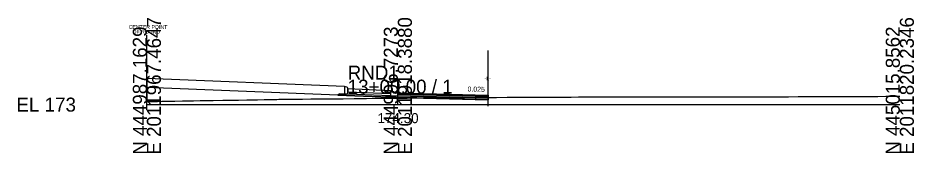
# Model space of a CAD drawing. Extents: x -26 to 153, y -10 to 6017.
# Drawn here: x -25.7 to 152.8, y 5990.3 to 6017.3 of the extents above; entities that cross this region are included whole.
import ezdxf

# ---------------------------------------------------------------- set-up
doc = ezdxf.new("R2010")
doc.units = 0
for name, color, linetype in [('Exist Cross Section Cell', 7, 'Continuous'), ('Exist XS Ground Line', 7, 'Continuous'), ('Prop CMT Conc Surface', 7, 'Continuous'), ('Prop CMT Concrete Structures', 7, 'Continuous'), ('Prop CMT Pvmt Course 1', 7, 'Continuous'), ('Prop CMT Pvmt Course 1 CG', 7, 'Continuous'), ('Prop CMT Pvmt Course 2', 7, 'Continuous'), ('Prop CMT Pvmt Course 3', 7, 'Continuous'), ('Prop CMT Pvmt Surface', 7, 'Continuous'), ('Prop CMT Shear Line', 7, 'Continuous'), ('Prop CMT Shear Line Text', 7, 'Continuous'), ('Prop CMT Slope Grass', 7, 'Continuous'), ('Prop CMT Subgrade Earthwork', 7, 'Continuous'), ('Prop XS Earthwork Shape', 7, 'Continuous'), ('Prop XS SE Text', 7, 'Continuous'), ('Scratch_Level_1', 7, 'Continuous')]:
    doc.layers.add(name, color=color, linetype=linetype)

msp = doc.modelspace()

# ---------------------------------------------------------------- linework, layer by layer
at = {"layer": 'Exist Cross Section Cell'}
for p, q in [((50, 6000), (50, 6004.99)), ((0, 6000), (50, 6000)), ((50, 6000), (150, 6000))]:
    msp.add_line(p, q, dxfattribs=at)
at = {"layer": 'Exist XS Ground Line'}
msp.add_lwpolyline([(0, 6000.62), (0.45, 6000.63), (2.11, 6000.65), (3, 6000.67), (4.98, 6000.7), (5.55, 6000.71), (7.12, 6000.74), (8.1, 6000.76), (9.26, 6000.78), (10.64, 6000.81), (12.71, 6000.84), (13.19, 6000.85), (15.11, 6000.88), (15.9, 6000.89), (18.28, 6000.92), (19.89, 6000.95), (20.83, 6000.96), (22.02, 6000.98), (23.38, 6001.01), (24.17, 6001.02), (25.92, 6001.05), (26.29, 6001.06), (28.47, 6001.1), (30.56, 6001.12), (31.03, 6001.12), (32.69, 6001.14), (33.56, 6001.15), (34.86, 6001.16), (36.11, 6001.17), (36.95, 6001.18), (38.67, 6001.19), (39.09, 6001.19), (41.27, 6001.21), (43.35, 6001.23), (43.76, 6001.24), (45.48, 6001.26), (46.3, 6001.26), (47.61, 6001.28), (48.85, 6001.29), (50, 6001.3), (51.4, 6001.31), (51.87, 6001.32), (54.3, 6001.34), (55.99, 6001.35), (56.7, 6001.36), (58.04, 6001.37), (59.42, 6001.38), (60.16, 6001.39), (62.35, 6001.41), (63.53, 6001.42), (64.61, 6001.43), (65.76, 6001.43), (66.62, 6001.43), (67.07, 6001.43), (67.43, 6001.43), (69.22, 6001.44), (69.65, 6001.45), (71.78, 6001.46), (73.03, 6001.46), (74.32, 6001.47), (75.25, 6001.47), (76.79, 6001.47), (77.45, 6001.47), (79.59, 6001.48), (80.49, 6001.48), (81.95, 6001.5), (82.32, 6001.5), (84.52, 6001.52), (85.98, 6001.53), (87.06, 6001.53), (88.11, 6001.53), (89.6, 6001.54), (91.84, 6001.55), (92.38, 6001.55), (93.51, 6001.55), (94.98, 6001.55), (97.24, 6001.55), (98.77, 6001.56), (99.78, 6001.56), (101.3, 6001.56), (102.33, 6001.56), (104.45, 6001.57), (105.16, 6001.57), (106.62, 6001.57), (107.64, 6001.57), (110, 6001.57), (111.55, 6001.57), (112.53, 6001.57), (113.94, 6001.57), (115.07, 6001.57), (117.12, 6001.56), (117.63, 6001.56), (119.76, 6001.55), (120.26, 6001.55), (122.71, 6001.56), (123.44, 6001.57), (125.26, 6001.58), (126.6, 6001.59), (127.79, 6001.59), (129.78, 6001.6), (130.35, 6001.6), (132.9, 6001.61), (135.08, 6001.61), (135.71, 6001.61), (137.37, 6001.62), (138.48, 6001.62), (139.92, 6001.63), (141.52, 6001.64), (142.3, 6001.64), (143.1, 6001.64), (144.29, 6001.65), (144.69, 6001.65), (145.62, 6001.65), (147.19, 6001.66), (147.51, 6001.66), (150, 6001.66)], dxfattribs=at)
at = {"layer": 'Prop CMT Conc Surface'}
for points in [[(40, 6003.31), (39.96, 6003.41), (39.85, 6003.46), (39.34, 6003.64)], [(40, 6003.14), (40, 6003.31)], [(50, 6002.35), (49.25, 6002.37), (49.25, 6002.53), (48.5, 6002.78)]]:
    msp.add_lwpolyline(points, dxfattribs=at)
at = {"layer": 'Prop CMT Concrete Structures'}
for points in [[(40, 6003.31), (39.96, 6003.41), (39.85, 6003.46), (39.34, 6003.64)], [(39.34, 6003.64), (39.34, 6002.14)], [(40, 6003.14), (40, 6003.31)], [(40, 6002.14), (40, 6003.14)], [(40, 6003.14), (40, 6002.56)], [(48.5, 6002.78), (40, 6003.13)], [(40, 6002.54), (48.5, 6002.2)], [(50, 6002.35), (49.25, 6002.37), (49.25, 6002.53), (48.5, 6002.78)], [(48.5, 6002.78), (48.5, 6001.8)], [(48.5, 6002.2), (48.5, 6002.78)], [(50, 6001.77), (50, 6002.35)], [(39.34, 6002.14), (40, 6002.14)], [(48.5, 6001.8), (50, 6001.77)]]:
    msp.add_lwpolyline(points, dxfattribs=at)
at = {"layer": 'Prop CMT Pvmt Course 1'}
for points in [[(50, 6002.35), (68, 6001.9)], [(50, 6002.1), (50, 6002.35)], [(68, 6001.65), (50, 6002.1)], [(68, 6001.9), (68, 6001.65)]]:
    msp.add_lwpolyline(points, dxfattribs=at)
msp.add_lwpolyline([(50, 6002.1), (50, 6002.22), (50, 6002.22), (50, 6002.1)], close=True, dxfattribs=at)
at = {"layer": 'Prop CMT Pvmt Course 1 CG'}
for points in [[(50, 6001.43), (50, 6001.77)], [(68, 6000.98), (68, 6001.31)]]:
    msp.add_lwpolyline(points, dxfattribs=at)
at = {"layer": 'Prop CMT Pvmt Course 2'}
for points in [[(50, 6001.77), (50, 6002.1)], [(50, 6002.1), (68, 6001.65)], [(68, 6001.31), (50, 6001.77)], [(68, 6001.65), (68, 6001.31)]]:
    msp.add_lwpolyline(points, dxfattribs=at)
at = {"layer": 'Prop CMT Pvmt Course 3'}
for points in [[(40, 6002.14), (48.5, 6001.8)], [(50, 6001.77), (68, 6001.31)], [(50, 6001.43), (50, 6001.77)], [(68, 6000.98), (50, 6001.43)], [(68, 6001.31), (68, 6000.98)]]:
    msp.add_lwpolyline(points, dxfattribs=at)
at = {"layer": 'Prop CMT Pvmt Surface'}
msp.add_lwpolyline([(50, 6002.35), (68, 6001.9)], dxfattribs=at)
at = {"layer": 'Prop CMT Shear Line'}
for p, q in [((0, 5998.89), (0, 6013.89)), ((68, 5999.72), (68, 6004.74))]:
    msp.add_line(p, q, dxfattribs=at)
at = {"layer": 'Prop CMT Slope Grass'}
for p, q in [((39.34, 6003.63), (0, 6005.2)), ((38.06, 6001.91), (0, 6003.43))]:
    msp.add_line(p, q, dxfattribs=at)
at = {"layer": 'Prop CMT Subgrade Earthwork'}
for p, q in [((0, 6005.2), (0, 6000.62)), ((38.34, 6002.18), (38.06, 6001.91)), ((68, 6001.9), (68, 6001.44)), ((68, 6000.98), (68, 6001.44))]:
    msp.add_line(p, q, dxfattribs=at)
for points in [[(38.06, 6001.91), (50, 6001.43)], [(38.34, 6002.18), (39.34, 6002.14)], [(50, 6001.43), (68, 6000.98)]]:
    msp.add_lwpolyline(points, dxfattribs=at)
at = {"layer": 'Prop XS Earthwork Shape'}
for points in [[(50, 6001.3), (51.4, 6001.31), (51.87, 6001.32), (53.8, 6001.34), (50, 6001.43), (38.06, 6001.91), (0, 6003.43), (0, 6000.62), (0.45, 6000.63), (2.11, 6000.65), (3, 6000.67), (4.98, 6000.7), (5.55, 6000.71), (7.12, 6000.74), (8.1, 6000.76), (9.26, 6000.78), (10.64, 6000.81), (12.71, 6000.84), (13.19, 6000.85), (15.11, 6000.88), (15.9, 6000.89), (18.28, 6000.92), (19.89, 6000.95), (20.83, 6000.96), (22.02, 6000.98), (23.38, 6001.01), (24.17, 6001.02), (25.92, 6001.05), (26.29, 6001.06), (28.47, 6001.1), (30.56, 6001.12), (31.03, 6001.12), (32.69, 6001.14), (33.56, 6001.15), (34.86, 6001.16), (36.11, 6001.17), (36.95, 6001.18), (38.67, 6001.19), (39.09, 6001.19), (41.27, 6001.21), (43.35, 6001.23), (43.76, 6001.24), (45.48, 6001.26), (46.3, 6001.26), (47.61, 6001.28), (48.85, 6001.29)], [(66.62, 6001.43), (67.07, 6001.43), (67.43, 6001.43), (68, 6001.44), (68, 6000.98), (53.8, 6001.34), (54.3, 6001.34), (55.99, 6001.35), (56.7, 6001.36), (58.04, 6001.37), (59.42, 6001.38), (60.16, 6001.39), (62.35, 6001.41), (63.53, 6001.42), (64.61, 6001.43), (65.76, 6001.43)]]:
    msp.add_lwpolyline(points, close=True, dxfattribs=at)
at = {"layer": 'Scratch_Level_1'}
msp.add_line((68, 6001.55), (68, 6010.81), dxfattribs=at)

# ---------------------------------------------------------------- texts
at = {"layer": 'Exist Cross Section Cell'}
for s, p in [('E 2011967.4647', (2.8, 5990)), ('E 2011918.3880', (52.8, 5990)), ('E 2011820.2346', (152.8, 5990)), ('N 444987.1629', (0, 5990)), ('N 444996.7273', (50, 5990)), ('N 445015.8562', (150, 5990))]:
    msp.add_text(s, height=2.8, rotation=90, dxfattribs=at).set_placement(p)
for s, p in [('RND1', (40, 6004.99)), ('13+00.00 / 1', (40, 6002.19)), ('EL 173', (-26, 5998.6))]:
    msp.add_text(s, height=2.8, dxfattribs=at).set_placement(p)
at = {"layer": 'Exist XS Ground Line'}
msp.add_text('174.30', height=2, dxfattribs=at).set_placement((45.95, 5996.3))
at = {"layer": 'Prop CMT Shear Line Text'}
for s, p in [('CENTER POINT', (-3.64, 6015.14)), ('OF ROUND', (-2.88, 6014.17)), ('-L-', (67.27, 6004.85))]:
    msp.add_text(s, height=0.75, dxfattribs=at).set_placement(p)
at = {"layer": 'Prop XS SE Text'}
msp.add_text('0.025', height=1, rotation=358.5613, dxfattribs=at).set_placement((63.87, 6002.63))

doc.saveas('drawing.dxf')
